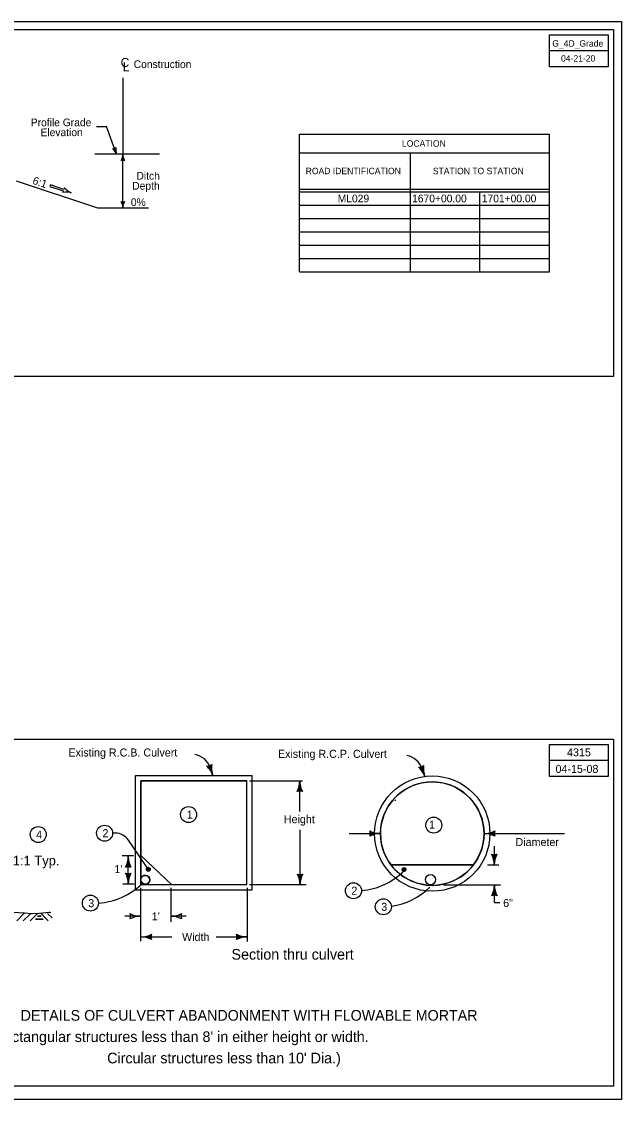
# Model space of a CAD drawing. Extents: x 4574 to 81668, y 5908 to 13780.
# Drawn here: x 12144 to 13268, y 7924 to 9944 of the extents above; entities that cross this region are included whole.
import ezdxf

# ---------------------------------------------------------------- set-up
doc = ezdxf.new("R2010")
doc.units = 0
for name, color, linetype in [('Cell', 7, 'Continuous'), ('dsnCellElements', 7, 'Continuous'), ('DsnShtRevisedText', 7, 'Continuous'), ('dsnStdBorder', 7, 'Continuous'), ('dsnStdLabel', 7, 'Continuous'), ('dsnStdTable', 7, 'Continuous'), ('dsnTextFinalPlan', 7, 'Continuous'), ('dsnTextTabulation', 7, 'Continuous'), ('Level 1', 7, 'Continuous'), ('SheetBorder', 7, 'Continuous')]:
    doc.layers.add(name, color=color, linetype=linetype)

msp = doc.modelspace()

# ---------------------------------------------------------------- linework, layer by layer
at = {"layer": 'Cell'}
for p, q in [((12133.5, 9645.5), (12285.8, 9594.8)), ((12285.8, 9594.8), (12381.5, 9594.8))]:
    msp.add_line(p, q, dxfattribs=at)
at = {"layer": 'dsnCellElements'}
for p, q in [((12502.1, 8531.4), (12495.6, 8549.5)), ((12899.2, 8529.3), (12892.6, 8547.4)), ((12357.4, 8316.9), (12357.4, 8531.4)), ((12357.4, 8531.4), (12576.1, 8531.4)), ((12576.1, 8316.9), (12576.1, 8531.4)), ((12367.5, 8327), (12367.5, 8521.3)), ((12367.5, 8521.3), (12566, 8521.3)), ((12566, 8327), (12566, 8521.3)), ((12570.5, 8521), (12670.1, 8521)), ((12664.9, 8463.4), (12664.9, 8521)), ((12664.9, 8521), (12664.9, 8501.8)), ((12665.5, 8326.7), (12665.5, 8429)), ((12319.2, 8423), (12314.4, 8423)), ((12381.3, 8355.2), (12344, 8409.9)), ((12757.2, 8422.2), (12816.1, 8422.2)), ((12816.1, 8422.2), (12796.9, 8422.2)), ((13010.1, 8422.2), (13160.6, 8422.2)), ((13010.1, 8422.2), (13029.3, 8422.2)), ((13029.5, 8363.1), (13029.5, 8398.7)), ((12332.1, 8381.1), (12353.2, 8381.1)), ((12343.7, 8379), (12343.7, 8359.8)), ((12343.7, 8327.9), (12343.7, 8379)), ((12367.5, 8380.9), (12424.7, 8327)), ((12836, 8363.4), (12984.5, 8363.4)), ((13016.9, 8363.4), (13038, 8363.4)), ((13029.4, 8363.6), (13029.4, 8382.8)), ((12343.7, 8327.9), (12343.7, 8347.1)), ((12665.6, 8326.3), (12665.6, 8345.5)), ((12333.2, 8327.9), (12354.7, 8327.9)), ((12367.5, 8327), (12566, 8327)), ((12570.5, 8326.6), (12676.9, 8326.6)), ((12934.4, 8326.2), (13040.9, 8326.2)), ((13029.5, 8292.8), (13029.5, 8326.2)), ((13029.6, 8325.9), (13029.6, 8306.7)), ((12357.4, 8316.9), (12576.1, 8316.9)), ((12367.5, 8220.9), (12367.5, 8320.8)), ((12423.8, 8256.6), (12423.8, 8320.8)), ((12566.8, 8219.9), (12566.8, 8320.8)), ((13029.5, 8292.8), (13039.5, 8292.8)), ((12126.8, 8275.1), (12149.3, 8273.7)), ((12148.8, 8272.9), (12134.7, 8258.8)), ((12161.3, 8272.7), (12147.1, 8258.5)), ((12149.5, 8273.7), (12162.7, 8272.3)), ((12174.3, 8272.9), (12160.1, 8258.8)), ((12163.5, 8272.3), (12177.3, 8272.9)), ((12180.3, 8267.4), (12173.7, 8267.4)), ((12173.7, 8267.4), (12180.3, 8267.4)), ((12177.6, 8273), (12195.5, 8274.7)), ((12179.7, 8272.9), (12193.8, 8258.8)), ((12192.7, 8272.7), (12201.2, 8264.2)), ((12196.3, 8274.7), (12198.9, 8274.5)), ((12367.3, 8267.2), (12337.4, 8267.2)), ((12452, 8267.2), (12423.3, 8267.2)), ((12184.1, 8261.6), (12169.9, 8261.6)), ((12169.9, 8261.6), (12184.1, 8261.6)), ((12367.5, 8228.6), (12386.7, 8228.6)), ((12367.5, 8228.6), (12425.5, 8228.6)), ((12508.4, 8228.6), (12566.5, 8228.6)), ((12566.5, 8228.6), (12547.3, 8228.6))]:
    msp.add_line(p, q, dxfattribs=at)
for points in [[(12499, 8550.3), (12495.9, 8548.4), (12492.3, 8547.9), (12495.7, 8544.5), (12499.5, 8538.7), (12498.6, 8546.1), (12498.8, 8549.6), (12496.2, 8547.8), (12493.9, 8547.3), (12496.1, 8545.1), (12498.3, 8541.9), (12498, 8546), (12498, 8548.3), (12495.2, 8546.8), (12497.3, 8544.6), (12497.2, 8546.9), (12496.2, 8546.6), (12496.9, 8545.7)], [(12896.1, 8548.2), (12893, 8546.3), (12889.4, 8545.8), (12892.8, 8542.5), (12896.5, 8536.6), (12895.6, 8544), (12895.9, 8547.5), (12893.2, 8545.7), (12890.9, 8545.2), (12893.2, 8543), (12895.4, 8539.8), (12895.1, 8543.9), (12895.1, 8546.2), (12892.3, 8544.8), (12894.4, 8542.5), (12894.3, 8544.8), (12893.3, 8544.5), (12893.9, 8543.6)], [(12661.4, 8502.2), (12665, 8502.9), (12668.6, 8502.1), (12666.5, 8506.4), (12665, 8513.3), (12663.2, 8505.9), (12661.8, 8502.8), (12665, 8503.6), (12667.3, 8503.3), (12665.9, 8506.1), (12665, 8509.9), (12663.8, 8505.8), (12663.1, 8503.7), (12666.1, 8504.1), (12665, 8506.9), (12664.3, 8504.7), (12665.3, 8504.7), (12665, 8505.7)], [(12843, 8483.6), (12844.8, 8485.4)], [(12797.3, 8425.8), (12798, 8422.2), (12797.2, 8418.6), (12801.5, 8420.6), (12808.4, 8422.2), (12801, 8423.9), (12797.9, 8425.3), (12798.6, 8422.2), (12798.3, 8419.9), (12801.2, 8421.2), (12805, 8422.2), (12800.9, 8423.4), (12798.8, 8424.1), (12799.2, 8421), (12802, 8422.2), (12799.8, 8422.9), (12799.8, 8421.8), (12800.8, 8422.2)], [(13028.9, 8418.6), (13028.2, 8422.2), (13028.9, 8425.8), (13024.6, 8423.7), (13017.8, 8422.2), (13025.2, 8420.5), (13028.3, 8419.1), (13027.5, 8422.2), (13027.8, 8424.5), (13025, 8423.2), (13021.2, 8422.2), (13025.3, 8421), (13027.4, 8420.3), (13027, 8423.4), (13024.2, 8422.2), (13026.4, 8421.5), (13026.4, 8422.6), (13025.4, 8422.2)], [(12340.2, 8360.2), (12343.7, 8360.9), (12347.3, 8360.2), (12345.3, 8364.5), (12343.7, 8371.3), (12342, 8364), (12340.6, 8360.8), (12343.7, 8361.6), (12346, 8361.3), (12344.7, 8364.1), (12343.7, 8367.9), (12342.6, 8363.9), (12341.8, 8361.8), (12344.9, 8362.2), (12343.7, 8365), (12343, 8362.8), (12344.1, 8362.7), (12343.8, 8363.8)], [(12833, 8367.5), (12833, 8367.5)], [(13033, 8382.4), (13029.4, 8381.7), (13025.8, 8382.4), (13027.9, 8378.1), (13029.4, 8371.3), (13031.1, 8378.6), (13032.5, 8381.8), (13029.4, 8381), (13027.1, 8381.3), (13028.4, 8378.5), (13029.4, 8374.7), (13030.6, 8378.7), (13031.3, 8380.8), (13028.2, 8380.4), (13029.4, 8377.6), (13030.1, 8379.8), (13029, 8379.9), (13029.4, 8378.8)], [(12347.3, 8346.7), (12343.7, 8346), (12340.1, 8346.8), (12342.2, 8342.5), (12343.7, 8335.6), (12345.4, 8343), (12346.8, 8346.1), (12343.7, 8345.4), (12341.4, 8345.7), (12342.7, 8342.8), (12343.7, 8339), (12344.9, 8343.1), (12345.6, 8345.2), (12342.5, 8344.8), (12343.7, 8342), (12344.4, 8344.2), (12343.3, 8344.2), (12343.7, 8343.2)], [(12381.6, 8358.4), (12380.4, 8357.8), (12378.6, 8357.3), (12378.2, 8355.4), (12378.5, 8353.8), (12379.7, 8352.3), (12381.4, 8352.4), (12383.3, 8352.7), (12384.1, 8354.1), (12384.3, 8355.7), (12383.2, 8357.7), (12381.9, 8357.9), (12380, 8357.4), (12378.5, 8356.2), (12378.6, 8354.5), (12379.7, 8353.1), (12381.4, 8352.9), (12383.2, 8353.3), (12383.5, 8354.3), (12383.9, 8355.6), (12383, 8357.1), (12381.7, 8357.1), (12380.2, 8356.8), (12379, 8355.9), (12379.6, 8354.4), (12380.8, 8353.5), (12382.3, 8353.5), (12382.7, 8354.3), (12383.2, 8355.2), (12382.4, 8356.5), (12381.3, 8356.7), (12380.3, 8356.2), (12380.2, 8355.1), (12380.7, 8354.2), (12381.8, 8354), (12382.3, 8354.4), (12382.6, 8355), (12382, 8355.9), (12381.3, 8356.1), (12380.6, 8355.7), (12380.7, 8355.1), (12381.2, 8354.7), (12382, 8354.7), (12382, 8355.2), (12381.3, 8355.5)], [(12669.1, 8345.2), (12665.6, 8344.4), (12662, 8345.2), (12664, 8340.9), (12665.6, 8334.1), (12667.3, 8341.4), (12668.7, 8344.5), (12665.6, 8343.8), (12663.3, 8344.1), (12664.6, 8341.2), (12665.6, 8337.5), (12666.7, 8341.5), (12667.5, 8343.6), (12664.4, 8343.2), (12665.6, 8340.4), (12666.3, 8342.6), (12665.2, 8342.6), (12665.5, 8341.6)], [(12860.6, 8358), (12859.4, 8357.5), (12857.5, 8356.9), (12857.2, 8355), (12857.4, 8353.4), (12858.6, 8351.9), (12860.4, 8352), (12862.2, 8352.3), (12863.1, 8353.8), (12863.3, 8355.3), (12862.2, 8357.3), (12860.8, 8357.5), (12859, 8357), (12857.5, 8355.9), (12857.5, 8354.1), (12858.7, 8352.7), (12860.3, 8352.5), (12862.2, 8352.9), (12862.5, 8353.9), (12862.8, 8355.2), (12862, 8356.7), (12860.6, 8356.7), (12859.1, 8356.4), (12858, 8355.6), (12858.6, 8354), (12859.7, 8353.1), (12861.3, 8353.1), (12861.6, 8353.9), (12862.1, 8354.9), (12861.4, 8356.1), (12860.2, 8356.3), (12859.2, 8355.8), (12859.2, 8354.7), (12859.7, 8353.9), (12860.7, 8353.6), (12861.2, 8354), (12861.5, 8354.6), (12861, 8355.5), (12860.3, 8355.7), (12859.5, 8355.3), (12859.7, 8354.7), (12860.2, 8354.3), (12860.9, 8354.3), (12860.9, 8354.8), (12860.3, 8355.1)], [(13026, 8307.1), (13029.6, 8307.8), (13033.2, 8307), (13031.1, 8311.3), (13029.6, 8318.2), (13027.9, 8310.8), (13026.5, 8307.7), (13029.6, 8308.4), (13031.9, 8308.1), (13030.6, 8311), (13029.6, 8314.8), (13028.4, 8310.7), (13027.7, 8308.6), (13030.8, 8309), (13029.6, 8311.8), (13028.9, 8309.6), (13030, 8309.6), (13029.6, 8310.6)], [(12386.3, 8225), (12385.6, 8228.6), (12386.3, 8232.2), (12382, 8230.1), (12375.2, 8228.6), (12382.5, 8226.9), (12385.7, 8225.5), (12384.9, 8228.6), (12385.2, 8230.9), (12382.4, 8229.6), (12378.6, 8228.6), (12382.6, 8227.4), (12384.7, 8226.7), (12384.3, 8229.8), (12381.5, 8228.6), (12383.7, 8227.9), (12383.8, 8229), (12382.7, 8228.6)], [(12547.7, 8232.1), (12548.4, 8228.6), (12547.7, 8225), (12552, 8227), (12558.8, 8228.6), (12551.4, 8230.3), (12548.3, 8231.7), (12549.1, 8228.6), (12548.8, 8226.3), (12551.6, 8227.6), (12555.4, 8228.6), (12551.4, 8229.7), (12549.3, 8230.5), (12549.6, 8227.4), (12552.4, 8228.6), (12550.2, 8229.3), (12550.2, 8228.2), (12551.2, 8228.5)]]:
    msp.add_lwpolyline(points, dxfattribs=at)
for centre, radius in [((12913.1, 8422.2), 108), ((12913.1, 8422.2), 97), ((12456.7, 8457.9), 15), ((12915.9, 8438.1), 15), ((12175.1, 8420.5), 15), ((12299.4, 8423), 15), ((12375.6, 8335.7), 8.23), ((12381.3, 8355.2), 3.5), ((12860.3, 8354.8), 3.5), ((12909.7, 8335.9), 9.51), ((12765.6, 8315.2), 15), ((12272.7, 8291.9), 15), ((12821.5, 8285), 15)]:
    msp.add_circle(centre, radius, dxfattribs=at)
for centre, radius, start, end in [((12461.9, 8534.3), 36.9, 17.6823, 79.9899), ((12858.9, 8532.2), 36.9, 17.6823, 79.9899), ((12489.9, 8564.9), 16.4, 272.2666, 307.7334), ((12462.2, 8516.9), 42.5, 20, 48.0725), ((12542.1, 8545.9), 42.5, 171.9275, 200), ((12887, 8562.8), 16.4, 272.2666, 307.7334), ((12859.3, 8514.8), 42.5, 20, 48.0725), ((12939.1, 8543.8), 42.5, 171.9275, 200), ((12622.4, 8521), 42.5, 331.9275, 0), ((12707.4, 8521), 42.5, 180, 208.0725), ((12664.9, 8485.4), 16.4, 72.2666, 107.7334), ((12780.5, 8422.2), 16.4, 342.2666, 17.7334), ((12816.1, 8464.7), 42.5, 241.9275, 270), ((13010.1, 8464.7), 42.5, 270, 298.0725), ((13045.7, 8422.2), 16.4, 162.2666, 197.7334), ((12319.2, 8393), 30, 34.2688, 90), ((12816.1, 8379.7), 42.5, 90, 118.0725), ((13010.1, 8379.7), 42.5, 61.9275, 90), ((13029.4, 8399.2), 16.4, 252.2666, 287.7333), ((12986.9, 8363.6), 42.5, 0, 28.0725), ((13071.9, 8363.6), 42.5, 151.9275, 180), ((12301.2, 8379), 42.5, 331.9275, 0), ((12386.2, 8379), 42.5, 180, 208.0725), ((12343.7, 8343.4), 16.4, 72.2666, 107.7334), ((12343.7, 8363.5), 16.4, 252.2666, 287.7333), ((12301.2, 8327.9), 42.5, 0, 28.0725), ((12386.2, 8327.9), 42.5, 151.9275, 180), ((12665.6, 8362), 16.4, 252.2666, 287.7333), ((12623.1, 8326.3), 42.5, 0, 28.0725), ((12708.1, 8326.3), 42.5, 151.9275, 180), ((12769.6, 8443.8), 128.8, 274.9104, 314.6972), ((12279.4, 8420.5), 128.8, 273.6929, 314.6972), ((12987.1, 8325.9), 42.5, 331.9275, 0), ((13072.1, 8325.9), 42.5, 180, 208.0725), ((12817.9, 8413.4), 128.8, 278.3054, 314.6972), ((13029.6, 8290.3), 16.4, 72.2666, 107.7334), ((12149, 8268.7), 5, 84.0146, 86.4551), ((12163.2, 8277.2), 5, 264.0146, 272.8473), ((12177.1, 8277.9), 5, 272.8473, 275.5382), ((12195.9, 8269.7), 5, 85.9429, 95.5382), ((12331.5, 8267.2), 16.4, 342.2666, 17.7333), ((12367.1, 8309.7), 42.5, 241.9275, 270), ((12367.1, 8224.7), 42.5, 90, 118.0725), ((12423.3, 8309.7), 42.5, 270, 298.0725), ((12423.3, 8224.7), 42.5, 61.9275, 90), ((12458.9, 8267.2), 16.4, 162.2666, 197.7334), ((12367.5, 8271.1), 42.5, 270, 298.0725), ((12367.5, 8186.1), 42.5, 61.9275, 90), ((12403.1, 8228.6), 16.4, 162.2666, 197.7334), ((12530.9, 8228.6), 16.4, 342.2666, 17.7333), ((12566.5, 8271.1), 42.5, 241.9275, 270), ((12566.5, 8186.1), 42.5, 90, 118.0725)]:
    msp.add_arc(centre, radius, start, end, dxfattribs=at)
at = {"layer": 'DsnShtRevisedText'}
for p, q in [((13252.5, 8599), (13252.5, 8599)), ((12984.5, 8363.4), (12990.5, 8363.4))]:
    msp.add_line(p, q, dxfattribs=at)
at = {"layer": 'dsnStdBorder'}
for points in [[(10147.5, 9929), (13252.5, 9929), (13252.5, 9279), (10147.5, 9279), (10147.5, 9929)], [(13242.5, 9919), (13242.5, 9859), (13132.5, 9859), (13132.5, 9919), (13242.5, 9919), (13242.5, 9889), (13132.5, 9889)]]:
    msp.add_lwpolyline(points, dxfattribs=at)
at = {"layer": 'dsnStdLabel'}
for p, q in [((12284.4, 9747.4), (12302.8, 9747.4)), ((12321.7, 9695.6), (12302.8, 9747.4)), ((12197.9, 9637.8), (12197, 9635.1)), ((12223, 9629.5), (12197.9, 9637.8)), ((12197, 9635.1), (12222, 9626.7)), ((12222, 9626.7), (12221, 9623.5)), ((12224, 9632.6), (12223, 9629.5)), ((12237, 9623.3), (12237, 9623.3))]:
    msp.add_line(p, q, dxfattribs=at)
for centre, radius, start, end in [((12314.4, 9715.7), 9.85, 272.2661, 307.7328), ((12297.7, 9686.9), 25.5, 19.9995, 48.072), ((12345.6, 9704.3), 25.5, 171.927, 199.9995), ((12228.5, 9593.5), 30.9, 73.917, 103.947), ((12248, 9652.2), 30.9, 219.183, 249.213)]:
    msp.add_arc(centre, radius, start, end, dxfattribs=at)
at = {"layer": 'dsnStdTable'}
for p, q in [((12664.5, 9733), (13132.5, 9733)), ((12664.5, 9475), (12664.5, 9733)), ((13132.5, 9625), (13132.5, 9733)), ((12664.5, 9698), (13132.5, 9698)), ((12872.5, 9475), (12872.5, 9698)), ((12664.5, 9630), (13132.5, 9630)), ((12664.5, 9625), (12872.5, 9625)), ((12872.5, 9625), (13001.6, 9625)), ((13002.5, 9475), (13002.5, 9625)), ((13002.5, 9625), (13132.5, 9625)), ((13132.5, 9600), (13132.5, 9625)), ((12664.5, 9600), (13132.5, 9600)), ((13132.5, 9475), (13132.5, 9600)), ((12664.5, 9575), (13132.5, 9575)), ((12664.5, 9550), (13132.5, 9550)), ((12664.5, 9525), (13132.5, 9525)), ((12664.5, 9500), (13132.5, 9500)), ((12664.5, 9475), (13132.5, 9475))]:
    msp.add_line(p, q, dxfattribs=at)
at = {"layer": 'dsnTextFinalPlan'}
for p, q in [((12333.6, 9838.5), (12333.6, 9695.6)), ((12401.9, 9695.6), (12280.8, 9695.6)), ((12333.6, 9594.8), (12333.6, 9695.6))]:
    msp.add_line(p, q, dxfattribs=at)
for centre, radius, start, end in [((12308.1, 9695.6), 25.5, 331.9275, 360), ((12333.6, 9674.2), 9.85, 72.2666, 107.7334), ((12359.1, 9695.6), 25.5, 180, 208.0725), ((12333.6, 9616.2), 9.85, 252.2666, 287.7334), ((12308.1, 9594.8), 25.5, 0, 28.0725), ((12359.1, 9594.8), 25.5, 151.9275, 180)]:
    msp.add_arc(centre, radius, start, end, dxfattribs=at)
at = {"layer": 'Level 1'}
for p, q in [((12990.2, 8363.4), (12836, 8363.4)), ((12836, 8363.4), (12990.2, 8363.4))]:
    msp.add_line(p, q, dxfattribs=at)
for points in [[(10147.5, 8599), (13252.5, 8599), (13252.5, 7949), (10147.5, 7949), (10147.5, 8599)], [(13242.5, 8589), (13242.5, 8529), (13132.5, 8529), (13132.5, 8589), (13242.5, 8589), (13242.5, 8559), (13132.5, 8559)], [(12367.5, 8334.5), (12367.5, 8327), (12424.7, 8327), (12367.5, 8380.9), (12367.5, 8336.9)]]:
    msp.add_lwpolyline(points, dxfattribs=at)
msp.add_lwpolyline([(12566, 8327), (12566, 8521.3), (12367.5, 8521.3), (12367.5, 8380.9), (12424.7, 8327)], close=True, dxfattribs=at)
for centre, radius in [((12456.7, 8457.9), 15), ((12915.9, 8438.1), 15), ((12381.3, 8355.2), 3.5), ((12860.3, 8354.8), 3.5), ((12909.7, 8335.9), 9.51)]:
    msp.add_circle(centre, radius, dxfattribs=at)
for centre, radius, start, end in [((12913.1, 8422.2), 97, 322.6702, 217.3298), ((12913.1, 8422.2), 97, 217.3298, 322.6702), ((12375.6, 8335.7), 8.23, 188.3205, 171.6795)]:
    msp.add_arc(centre, radius, start, end, dxfattribs=at)
at = {"layer": 'SheetBorder'}
msp.add_lwpolyline([(10132.5, 9944), (13267.5, 9944), (13267.5, 7924), (10132.5, 7924)], close=True, dxfattribs=at)

# ---------------------------------------------------------------- texts
at = {"layer": 'dsnCellElements'}
msp.add_text('1:1 Typ.', height=18.09, dxfattribs=at).set_placement((12127.4, 8362.6))
at = {"layer": 'DsnShtRevisedText'}
for s, height, p in [('Existing R.C.B. Culvert', 15, (12231.6, 8566.7)), ('Existing R.C.P. Culvert', 15, (12624.1, 8564.2)), ('1', 15, (12453.3, 8450.4)), ('Height', 15, (12635.1, 8441.7)), ('1', 15, (12907.1, 8431.5)), ('2', 15, (12295.4, 8415.5)), ('Diameter', 15, (13069.1, 8398.9)), ("1'", 15, (12317.7, 8348.1)), ('2', 15, (12761.7, 8307.7)), ('3', 15, (12268.8, 8284.4)), ('3', 15, (12817.6, 8277.5)), ('6"', 15, (13046, 8284.6)), ("1'", 15, (12387.7, 8259.7)), ('Width', 15, (12444.5, 8221)), ('DETAILS OF CULVERT ABANDONMENT WITH FLOWABLE MORTAR ', 20, (12142.1, 8071.6)), ("(Rectangular structures less than 8' in either height or width. ", 20, (12082.9, 8031.6)), ("Circular structures less than 10' Dia.) ", 20, (12304.2, 7991.6))]:
    msp.add_text(s, height=height, dxfattribs=at).set_placement(p)
for s, height, rotation, p in [('4', 15, 359.9815, (12171.2, 8413)), ('Section thru culvert', 20, 359.9816, (12537.1, 8186))]:
    msp.add_text(s, height=height, rotation=rotation, dxfattribs=at).set_placement(p)
at = {"layer": 'dsnStdLabel'}
for s, p in [('C', (12329.4, 9858.9)), ('L', (12333.4, 9850.6))]:
    msp.add_text(s, height=16.8, dxfattribs=at).set_placement(p)
for s, rotation, p in [('Profile Grade', 0.0419, (12161.1, 9747.8)), ('Elevation', 0.0419, (12179.3, 9729.2)), ('6:1', 341.565, (12163.3, 9640.2))]:
    msp.add_text(s, height=14.4, rotation=rotation, dxfattribs=at).set_placement(p)
at = {"layer": 'dsnStdTable'}
for s, p in [('LOCATION', (12856.4, 9709.5)), ('ROAD IDENTIFICATION', (12676.1, 9658)), ('STATION TO STATION', (12914.2, 9658))]:
    msp.add_text(s, height=12, dxfattribs=at).set_placement(p)
at = {"layer": 'dsnTextFinalPlan'}
for s, p in [('Construction', (12353.9, 9856.9)), ('Ditch', (12359, 9647.7)), ('Depth', (12351.1, 9629.1)), ('0%', (12348.6, 9598.3))]:
    msp.add_text(s, height=14.4, dxfattribs=at).set_placement(p)
at = {"layer": 'dsnTextTabulation'}
for s, height, p in [('G_4D_Grade', 12, (13138, 9897)), ('04-21-20', 12, (13154.4, 9869)), ('4315', 15, (13165.6, 8567)), ('04-15-08', 15, (13144.1, 8536))]:
    msp.add_text(s, height=height, dxfattribs=at).set_placement(p)
at = {"layer": 'SheetBorder'}
for s, p in [('ML029', (12736, 9605.3)), ('1670+00.00', (12875.4, 9605.3)), ('1701+00.00', (13005.9, 9605.3))]:
    msp.add_text(s, height=14.4, dxfattribs=at).set_placement(p)

doc.saveas('drawing.dxf')
